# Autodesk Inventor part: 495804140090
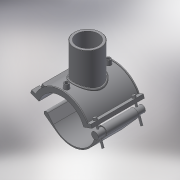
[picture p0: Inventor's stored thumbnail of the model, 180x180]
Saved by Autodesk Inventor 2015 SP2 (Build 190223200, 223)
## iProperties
Created: 2017-07
Part Number: 495804140090
Material: Generic
Description: PLASSON BRANCH SADDLE 140-90
Document SubType Name: Modeling
Designer: KIM
Density: 1 g/cm^3
Appearance: Default
Author: KIM
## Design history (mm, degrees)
derived "495804.ipt"
feature "Solid1::495804.ipt"
feature "Solid2::495804.ipt"
tag "TaggingFeature1"
body "Solid1"
body "Solid2"
other parameters: "d2" = 208.8, "d3" = 35, "d4" = 176, "d5" = 0, "d6" = 0.1, "d8" = 0, "d19" = 6, "d20" = 6, "d21" = 105.6, "d23" = 0, "d24" = 52.8, "d26" = 0, "d27" = 3, "d28" = 3, "d29" = 3, "d30" = 46.66667, "d31" = 6, "d32" = 0, "d33" = 0, "d34" = 0.6, "d40" = 88.4, "d41" = 99, "d43" = 0, "d45" = 0, "d50" = 0, "d70" = 15, "d72" = 0, "d73" = 6, "d75" = 5, "d76" = 0, "d77" = 7, "d79" = 15, "d80" = 70.4, "d82" = 5 deg, "d84" = 4, "d85" = 14, "d86" = 0, "d87" = 3, "d88" = 0, "d89" = 1, "d90" = 1, "d91" = 140.8, "d92" = 0, "d93" = 0.5, "d94" = 73.68421, "d96" = 173.4, "d97" = 3.52, "d98" = 0, "d102" = 2.7, "d103" = 72, "d105" = 0, "d109" = -35, "d117" = 0.9, "d120" = 140 deg, "d121" = 24.228, "d122" = 20 deg, "d124" = 102, "d126" = 0, "d143" = 147, "d150" = 25.2, "d159" = 6, "d161" = 3.5, "d162" = 105.6, "d163" = 0, "d167" = 28, "d168" = 77.27273, "d173" = 1, "d176" = 20 deg, "d177" = 9.8, "d178" = 27, "d180" = 0, "d185" = 57.2, "d186" = 57.2, "d187" = 85, "d188" = 9, "d189" = 9.8, "d190" = 0, "d191" = 127.5, "d200" = 15, "d202" = 0, "d216" = 158.4, "d217" = 0, "d221" = 65.12, "d222" = 9.8, "d223" = 5.88, "d225" = 5.88, "d227" = 20.16, "d230" = 92.4, "d236" = 20 deg, "d237" = 92, "d238" = 20 deg, "d239" = 9.8, "B_" = 174, "H_" = 105, "L_" = 176, "d_t" = 6, "d148" = 3.5, "d160" = 3.5
